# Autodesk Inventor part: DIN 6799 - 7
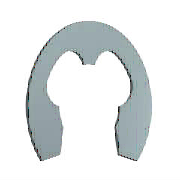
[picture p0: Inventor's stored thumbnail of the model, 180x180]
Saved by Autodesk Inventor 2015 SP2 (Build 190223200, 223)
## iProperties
Created: 2014-02
Part Number: DIN 6799 - 7
Material: Stahl, weich
Description: Sicherungsscheibe
Document SubType Name: Modeling
Standard: DIN 6799
Designer: rYan
Standards Organization: DIN
Language: de-DE
Size Designation: 7
Categories: <MemberInstance><Categories><Category DisplayName="Wellenteile" InternalName="7f7aeb1f-a693-4053-b835-cee3144e0d98" Mnemonic="SHFT"><Category DisplayName="Siche
Density: 7.85 g/cm^3
Appearance: Halbpoliert
IsCustomPart: 0
Author: rYan
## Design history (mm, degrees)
sketch "Skizze1"
  geometry: L1 (-0.7, 0.024)-(0, 0.024) reference; L2 (-3.206, 0)-(3.486, 0) reference; L3 (-3.208, -5.376)-(3.208, -5.376); L4 (0, 1.949)-(0, -3.479) reference; L5 (-4.2, -2.576)-(-3.514, -2.576); L6 (-0.7, 0.224)-(-0.7, 0.904); L7 (0, 3.174)-(2.53, 3.174); L8 (-3.208, -5.376)-(-4.091, -7.731); L9 (0, -0.476)-(-1.278, -0.476); L10 (3.208, -5.376)-(4.091, -7.731); L11 (4.2, -2.576)-(3.514, -2.576); L12 (0.7, 0.224)-(0.7, 0.904); C1 r 4 at (0, -3.976); A1 r 3.5 centre (0, -3.976) between (-3.315, -2.854) and (-3.208, -5.376); A2 r 0.7 centre (0, 0.224) between (-0.7, 0.224) and (0.7, 0.224); A3 r 7.15 centre (0, -3.976) between (5.948, -7.945) and (-5.948, -7.945); A4 r 5.6 centre (0, -3.976) between (-1.4, 1.446) and (-4.941, -1.341); A5 r 0.56 centre (-1.26, 0.904) between (-0.7, 0.904) and (-1.4, 1.446); A6 r 0.84 centre (-4.2, -1.736) between (-4.941, -1.341) and (-4.2, -2.576); A7 r 0.21 centre (-3.514, -2.786) between (-3.315, -2.854) and (-3.514, -2.576); A8 r 1.05 centre (-5.074, -7.362) between (-5.948, -7.945) and (-4.091, -7.731); A9 r 1.05 centre (5.074, -7.362) between (4.091, -7.731) and (5.948, -7.945); A10 r 3.5 centre (0, -3.976) between (3.208, -5.376) and (3.315, -2.854); A11 r 0.21 centre (3.514, -2.786) between (3.514, -2.576) and (3.315, -2.854); A12 r 0.84 centre (4.2, -1.736) between (4.2, -2.576) and (4.941, -1.341); A13 r 5.6 centre (0, -3.976) between (4.941, -1.341) and (1.4, 1.446); A14 r 0.56 centre (1.26, 0.904) between (1.4, 1.446) and (0.7, 0.904); 1 further point
  constraints: 30 point on circle, 20 end point, 15 centre point, 13 symmetric about line, 12 tangent, 8 point on line, 4 parallel, 2 coincident, 2 horizontal, 1 concentric, 1 perpendicular, 1 vertical alignment, 9 other
  dimensions: "d0" = 8 diameter of C1 (= WD); "d3" = 1.4 distance from line of A1.centre L3 (= 0.2 x ND); "d4" = 0.7 radius of A2 (= 0.1 x ND); "d5" = 14.3 diameter of A3 (= SD2); "d8" = 5.6 radius of A4 (= 0.8 x ND); "d9" = 1.4 distance from line of A1.centre L5 (= 0.2 x ND); "d10" = 0.56 radius of A5 (= 0.08 x ND); "d11" = 0.84 radius of A6 (= 0.12 x ND); "d12" = 0.21 radius of A7 (= 0.03 x ND); "d13" = 1.05 radius of A8 (= 0.15 x ND); "d14" = 3.5 distance from line of A1.centre L9 (= 0.5 x ND); "d15" = 3.5 radius of A1 (= 0.5 x ND)
extrude "Körper" new body sketch "Skizze1" distance "d16" = 0.9 (= SD); taper "d17" = 0 deg
workaxis "Work Axis1"
workaxis "Work Axis2"
workplane "Work Plane1"
body "Solid1"
other parameters: "ND" = 7 [user parameter; used in 14 equation terms], "SD" = 0.9 [user parameter; used in 1 equation term], "WD" = 8 [user parameter; used in 1 equation term], "d1" = 11.2 (= 1.6 x ND), "d2" = 7 (= ND), "SD2" = 14.3 [user parameter; used in 1 equation term], "d6" = 7 (= ND), "d7" = 1.05 (= 0.15 x ND), "d18" = 0, "d19" = 0, "d27" = 0, "d28" = 0, "WDMIN" = 7 [user parameter], "SNB" = 0.94 [user parameter], "WDMAX" = 9 [user parameter], "BUBRMI" = 1.2 [user parameter]
